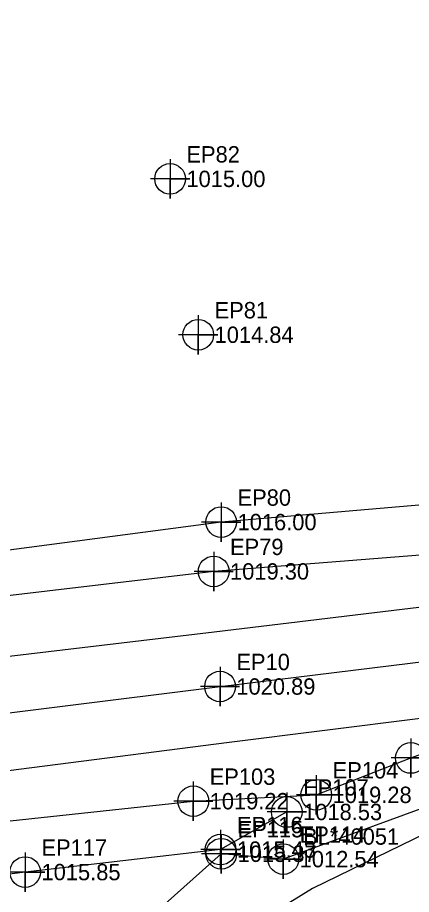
# Model space of a CAD drawing. Extents: x 1382561 to 1383039, y 884068 to 884307.
# Drawn here: x 1382691.1 to 1382751.3, y 884154.1 to 884288.1 of the extents above; entities that cross this region are included whole.
import ezdxf

# ---------------------------------------------------------------- set-up
doc = ezdxf.new("R2010")
doc.units = 0
for name, color, linetype in [('Exist DTM Breakline', 7, 'Continuous'), ('Exist DTM Breakline Cogo Comment', 7, 'Continuous'), ('Exist DTM Breakline Cogo Elevation', 7, 'Continuous'), ('Exist DTM Breakline Cogo Number', 7, 'Continuous'), ('Exist DTM Breakline Cogo Point CELL', 7, 'Continuous'), ('Exist DTM Crownline', 7, 'Continuous'), ('Exist DTM Crownline Cogo Elevation', 7, 'Continuous'), ('Exist DTM Crownline Cogo Number', 7, 'Continuous'), ('Exist DTM Crownline Cogo Point CELL', 7, 'Continuous'), ('Exist DTM Regular Point CELL', 7, 'Continuous'), ('Exist DTM Regular Point Cogo Elevation', 7, 'Continuous'), ('Exist DTM Regular Point Cogo Number', 7, 'Continuous'), ('Exist Hydro Stream or Body of Water', 7, 'Continuous'), ('Exist Roads EOP', 7, 'Continuous')]:
    doc.layers.add(name, color=color, linetype=linetype)

msp = doc.modelspace()

# ---------------------------------------------------------------- linework, layer by layer
at = {"layer": 'Exist DTM Breakline'}
for points in [[(1382806.7045, 884288.1336), (1382793.0575, 884267.4591), (1382781.8725, 884234.0918), (1382778.997, 884218.196), (1382773.7671, 884215.476), (1382722.2214, 884211.0337), (1382668.872, 884203.9756), (1382615.627, 884202.5184), (1382567.5113, 884196.1242)], [(1382774.3329, 884205.1982), (1382768.0574, 884207.1773), (1382721.0722, 884203.493), (1382670.0814, 884197.4905), (1382619.8383, 884190.0037), (1382569.9863, 884185.1279)], [(1382574.4485, 884150.6451), (1382626.0018, 884158.34), (1382674.2791, 884163.6957), (1382717.959, 884168.385), (1382736.7551, 884169.3534), (1382751.216, 884174.9855), (1382761.9845, 884178.8637)], [(1382765.9243, 884175.6081), (1382754.8134, 884167.9678), (1382731.7194, 884159.5309), (1382722.2333, 884160.3495), (1382705.5702, 884145.487), (1382682.8713, 884116.2267), (1382674.3334, 884104.2092), (1382674.6208, 884111.7647), (1382664.0032, 884106.0759), (1382669.8487, 884092.884)], [(1382732.2417, 884166.7349), (1382722.1245, 884160.9888), (1382692.2473, 884157.5499), (1382656.2039, 884152.9037), (1382627.5856, 884147.8988), (1382575.1219, 884143.3518)]]:
    msp.add_lwpolyline(points, dxfattribs=at)
at = {"layer": 'Exist DTM Breakline Cogo Point CELL'}
for points in [[(1382722.2214, 884214.0337), (1382722.2214, 884208.0337), (1382722.2214, 884211.0337), (1382725.2214, 884211.0337), (1382719.2214, 884211.0337)], [(1382721.0722, 884206.493), (1382721.0722, 884200.493), (1382721.0722, 884203.493), (1382724.0722, 884203.493), (1382718.0722, 884203.493)], [(1382751.216, 884177.9855), (1382751.216, 884171.9855), (1382751.216, 884174.9855), (1382754.216, 884174.9855), (1382748.216, 884174.9855)], [(1382736.7551, 884172.3534), (1382736.7551, 884166.3534), (1382736.7551, 884169.3534), (1382739.7551, 884169.3534), (1382733.7551, 884169.3534)], [(1382717.959, 884171.385), (1382717.959, 884165.385), (1382717.959, 884168.385), (1382720.959, 884168.385), (1382714.959, 884168.385)], [(1382732.2417, 884169.7349), (1382732.2417, 884163.7349), (1382732.2417, 884166.7349), (1382735.2417, 884166.7349), (1382729.2417, 884166.7349)], [(1382722.1245, 884163.9888), (1382722.1245, 884157.9888), (1382722.1245, 884160.9888), (1382725.1245, 884160.9888), (1382719.1245, 884160.9888)], [(1382722.2333, 884163.3495), (1382722.2333, 884157.3495), (1382722.2333, 884160.3495), (1382725.2333, 884160.3495), (1382719.2333, 884160.3495)], [(1382731.7194, 884162.5309), (1382731.7194, 884156.5309), (1382731.7194, 884159.5309), (1382734.7194, 884159.5309), (1382728.7194, 884159.5309)], [(1382692.2473, 884160.5499), (1382692.2473, 884154.5499), (1382692.2473, 884157.5499), (1382695.2473, 884157.5499), (1382689.2473, 884157.5499)]]:
    msp.add_lwpolyline(points, dxfattribs=at)
for centre in [(1382722.2214, 884211.0337), (1382721.0722, 884203.493), (1382751.216, 884174.9855), (1382736.7551, 884169.3534), (1382717.959, 884168.385), (1382732.2417, 884166.7349), (1382722.1245, 884160.9888), (1382722.2333, 884160.3495), (1382731.7194, 884159.5309), (1382692.2473, 884157.5499)]:
    msp.add_circle(centre, 2.344, dxfattribs=at)
at = {"layer": 'Exist DTM Crownline'}
msp.add_lwpolyline([(1382573.1626, 884167.9166), (1382622.8682, 884173.7315), (1382672.5741, 884179.7354), (1382722.0434, 884185.9092), (1382771.4612, 884191.9829)], dxfattribs=at)
at = {"layer": 'Exist DTM Crownline Cogo Point CELL'}
msp.add_lwpolyline([(1382722.0434, 884188.9092), (1382722.0434, 884182.9092), (1382722.0434, 884185.9092), (1382725.0434, 884185.9092), (1382719.0434, 884185.9092)], dxfattribs=at)
msp.add_circle((1382722.0434, 884185.9092), 2.344, dxfattribs=at)
at = {"layer": 'Exist DTM Regular Point CELL'}
for points in [[(1382714.404, 884266.4793), (1382714.404, 884260.4793), (1382714.404, 884263.4793), (1382717.404, 884263.4793), (1382711.404, 884263.4793)], [(1382718.7135, 884242.6607), (1382718.7135, 884236.6607), (1382718.7135, 884239.6607), (1382721.7135, 884239.6607), (1382715.7135, 884239.6607)]]:
    msp.add_lwpolyline(points, dxfattribs=at)
for centre in [(1382714.404, 884263.4793), (1382718.7135, 884239.6607)]:
    msp.add_circle(centre, 2.344, dxfattribs=at)
at = {"layer": 'Exist Hydro Stream or Body of Water'}
msp.add_lwpolyline([(1382815.7469, 884285.0295), (1382796.5538, 884263.5381), (1382784.2894, 884233.9786), (1382781.1386, 884206.3096), (1382772.3397, 884180.9543), (1382766.7799, 884172.9781), (1382757.421, 884165.3571), (1382736.1951, 884155.0402), (1382706.3401, 884136.6072), (1382689.3837, 884112.6314), (1382676.096, 884092.4493)], dxfattribs=at)
at = {"layer": 'Exist Roads EOP'}
for points in [[(1382572.4495, 884176.8659), (1382622.0271, 884182.499), (1382672.5956, 884188.515), (1382721.14, 884194.2421), (1382775.6714, 884200.8541)], [(1382574.0878, 884158.9549), (1382623.8158, 884164.9302), (1382674.5802, 884171.138), (1382723.4333, 884177.3901), (1382767.3133, 884182.9042)]]:
    msp.add_lwpolyline(points, dxfattribs=at)

# ---------------------------------------------------------------- texts
at = {"layer": 'Exist DTM Breakline Cogo Comment'}
msp.add_text('BL*40051', height=2.5, dxfattribs=at).set_placement((1382734.7417, 884161.7349))
at = {"layer": 'Exist DTM Breakline Cogo Elevation'}
for s, p in [('1016.00', (1382724.7214, 884209.7837)), ('1019.30', (1382723.5722, 884202.243)), ('1019.28', (1382739.2551, 884168.1034)), ('1019.22', (1382720.459, 884167.135)), ('1018.53', (1382734.7417, 884165.4849)), ('1015.43', (1382724.6245, 884159.7388)), ('1015.37', (1382724.7333, 884159.0995)), ('1012.54', (1382734.2194, 884158.2809)), ('1015.85', (1382694.7473, 884156.2999))]:
    msp.add_text(s, height=2.5, dxfattribs=at).set_placement(p)
at = {"layer": 'Exist DTM Breakline Cogo Number'}
for s, p in [('EP80', (1382724.7214, 884213.5337)), ('EP79', (1382723.5722, 884205.993)), ('EP104', (1382739.2551, 884171.8534)), ('EP103', (1382720.459, 884170.885)), ('EP107', (1382734.7417, 884169.2349)), ('EP116', (1382724.6245, 884163.4888)), ('EP115', (1382724.7333, 884162.8495)), ('EP114', (1382734.2194, 884162.0309)), ('EP117', (1382694.7473, 884160.0499))]:
    msp.add_text(s, height=2.5, dxfattribs=at).set_placement(p)
at = {"layer": 'Exist DTM Crownline Cogo Elevation'}
msp.add_text('1020.89', height=2.5, dxfattribs=at).set_placement((1382724.5434, 884184.6592))
at = {"layer": 'Exist DTM Crownline Cogo Number'}
msp.add_text('EP10', height=2.5, dxfattribs=at).set_placement((1382724.5434, 884188.4092))
at = {"layer": 'Exist DTM Regular Point Cogo Elevation'}
for s, p in [('1015.00', (1382716.904, 884262.2293)), ('1014.84', (1382721.2135, 884238.4107))]:
    msp.add_text(s, height=2.5, dxfattribs=at).set_placement(p)
at = {"layer": 'Exist DTM Regular Point Cogo Number'}
for s, p in [('EP82', (1382716.904, 884265.9793)), ('EP81', (1382721.2135, 884242.1607))]:
    msp.add_text(s, height=2.5, dxfattribs=at).set_placement(p)

doc.saveas('drawing.dxf')
